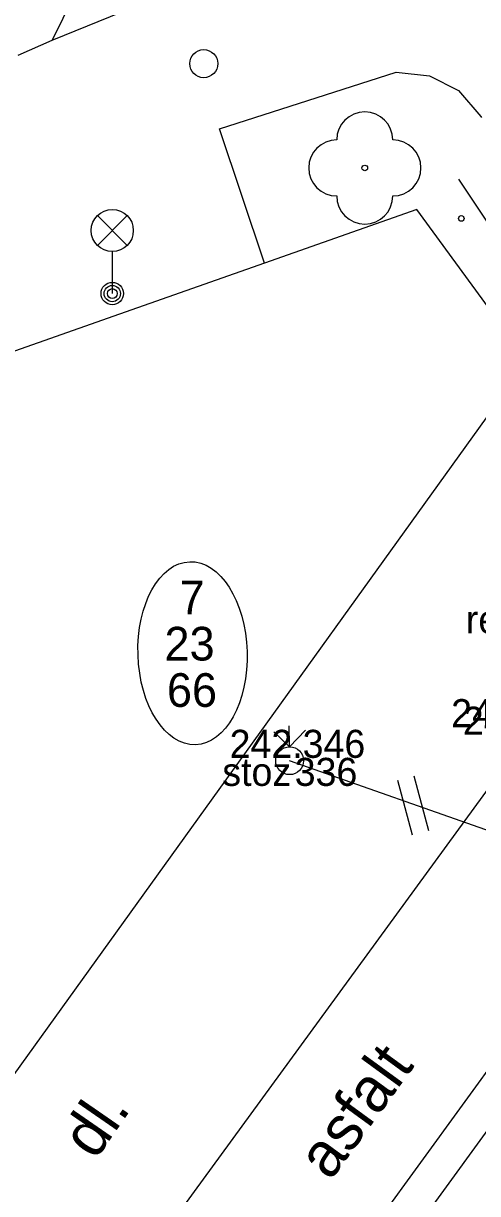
# Model space of a CAD drawing. Extents: x -599098 to -598820, y -1159597 to -1158744.
# Drawn here: x -598925.74 to -598917.65, y -1159386.24 to -1159365.37 of the extents above; entities that cross this region are included whole.
import ezdxf

# ---------------------------------------------------------------- set-up
doc = ezdxf.new("R2010")
doc.units = 0
for name, color, linetype in [('body', 7, 'Continuous'), ('druh pozemku stromy', 7, 'Continuous'), ('kresba', 7, 'Continuous'), ('kódy bodů', 7, 'Continuous'), ('popisy', 7, 'Continuous'), ('tram_koleje', 7, 'Continuous'), ('trol_detaily', 7, 'Continuous'), ('trol_převěsy', 7, 'Continuous'), ('trol_ved sloupy konzoly', 7, 'Continuous'), ('trol_čísla sloupů', 7, 'Continuous'), ('výšky bodů', 7, 'Continuous'), ('značky IS', 7, 'Continuous'), ('čísla bodů', 7, 'Continuous')]:
    doc.layers.add(name, color=color, linetype=linetype)

msp = doc.modelspace()

# ---------------------------------------------------------------- linework, layer by layer
at = {"layer": 'body'}
msp.add_line((-598920.909, -1159378.469), (-598920.909, -1159378.469), dxfattribs=at)
at = {"layer": 'druh pozemku stromy'}
msp.add_lwpolyline([(-598917.99, -1159368.15), (-598917.49, -1159368.9), (-598916.99, -1159368.15)], dxfattribs=at)
for centre in [(-598919.66, -1159367.95), (-598917.94, -1159368.85)]:
    msp.add_circle(centre, 0.05, dxfattribs=at)
for centre, start, end in [((-598919.66, -1159367.45), 0, 180), ((-598920.16, -1159367.95), 90, 270), ((-598919.16, -1159367.95), 270, 90), ((-598919.66, -1159368.45), 180, 0)]:
    msp.add_arc(centre, 0.5, start, end, dxfattribs=at)
at = {"layer": 'kresba'}
for p, q in [((-598925.23, -1159365.67), (-598919.84, -1159363.46)), ((-598925.84, -1159365.94), (-598925.23, -1159365.67)), ((-598934.54, -1159402.45), (-598916.76, -1159378.057)), ((-598915.031, -1159380.678), (-598951.27, -1159430.52))]:
    msp.add_line(p, q, dxfattribs=at)
for points in [[(-598922.624, -1159351.933), (-598922.69, -1159352.94), (-598922.97, -1159354.75), (-598923.44, -1159356.59), (-598924.02, -1159358.81), (-598924.53, -1159360.89), (-598924.62, -1159361.48), (-598924.61, -1159362.37), (-598924.56, -1159363.18), (-598924.65, -1159363.9), (-598924.85, -1159364.89), (-598925.23, -1159365.67)], [(-598921.45, -1159369.65), (-598922.25, -1159367.25), (-598919.1, -1159366.24)], [(-598919.1, -1159366.24), (-598918.51, -1159366.31), (-598917.99, -1159366.57), (-598917.59, -1159367.03), (-598917.58, -1159367.05)], [(-598918.73, -1159368.69), (-598921.45, -1159369.65), (-598924.03, -1159370.56), (-598935.33, -1159374.54), (-598938.26, -1159375.56), (-598940.5, -1159376.36), (-598944.27, -1159377.65), (-598946.87, -1159378.584)], [(-598937.39, -1159400.08), (-598916.76, -1159371.39), (-598918.73, -1159368.69)]]:
    msp.add_lwpolyline(points, dxfattribs=at)
at = {"layer": 'tram_koleje'}
msp.add_line((-598913.906, -1159380.188), (-598920.836, -1159389.728), dxfattribs=at)
at = {"layer": 'trol_detaily'}
for p, q in [((-598918.52, -1159379.769), (-598918.78, -1159378.793)), ((-598918.809, -1159379.846), (-598919.071, -1159378.87))]:
    msp.add_line(p, q, dxfattribs=at)
at = {"layer": 'trol_převěsy'}
msp.add_line((-598903.14, -1159384.83), (-598921, -1159378.52), dxfattribs=at)
at = {"layer": 'trol_ved sloupy konzoly'}
for q in [(-598921.01, -1159377.899), (-598920.718, -1159377.978), (-598921.279, -1159378.004)]:
    msp.add_line((-598921.004, -1159378.271), q, dxfattribs=at)
msp.add_circle((-598921, -1159378.52), 0.248, dxfattribs=at)
at = {"layer": 'trol_čísla sloupů'}
msp.add_ellipse((-598922.729, -1159376.603), major_axis=(0.051, -1.632), ratio=0.595913, dxfattribs=at)
at = {"layer": 'značky IS'}
for p, q in [((-598924.425, -1159369.33), (-598923.895, -1159368.8)), ((-598924.425, -1159368.8), (-598923.895, -1159369.33)), ((-598924.16, -1159369.44), (-598924.16, -1159370.19))]:
    msp.add_line(p, q, dxfattribs=at)
for centre, radius in [((-598922.53, -1159366.09), 0.25), ((-598924.16, -1159369.065), 0.375), ((-598924.16, -1159370.19), 0.2), ((-598924.16, -1159370.19), 0.145), ((-598924.16, -1159370.19), 0.0876)]:
    msp.add_circle(centre, radius, dxfattribs=at)

# ---------------------------------------------------------------- texts
at = {"layer": 'kódy bodů'}
for s, p in [('relDla', (-598917.859, -1159376.251)), ('stoz', (-598922.199, -1159378.969))]:
    msp.add_text(s, height=0.5, dxfattribs=at).set_placement(p)
at = {"layer": 'popisy'}
for s, rotation, p in [('asfalt', 53.9118, (-598920.275, -1159386.025)), ('dl.', 55.312, (-598924.46, -1159385.657))]:
    msp.add_text(s, height=0.8, rotation=rotation, dxfattribs=at).set_placement(p)
at = {"layer": 'trol_čísla sloupů'}
for s, p in [('7', (-598922.961, -1159375.907)), ('23', (-598923.229, -1159376.733)), ('66', (-598923.186, -1159377.56))]:
    msp.add_text(s, height=0.6, dxfattribs=at).set_placement(p)
at = {"layer": 'výšky bodů'}
for s, p in [('242.158', (-598918.122, -1159377.922)), ('242.045', (-598917.912, -1159378.057)), ('242.346', (-598922.069, -1159378.469))]:
    msp.add_text(s, height=0.5, dxfattribs=at).set_placement(p)
at = {"layer": 'čísla bodů'}
msp.add_text('336', height=0.5, dxfattribs=at).set_placement((-598920.909, -1159378.969))

doc.saveas('drawing.dxf')
